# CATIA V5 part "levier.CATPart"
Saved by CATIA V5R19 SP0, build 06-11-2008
Part number: levier
Bounding box of the stored display mesh (mm): x -169.833 to 461.251, y 540.167 to 782.211, z -45 to 45
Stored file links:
  C:\Users\Thibaud\Desktop\IFMA\thinkmotion\IAO\modele_catia\levier.CATPart
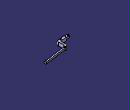
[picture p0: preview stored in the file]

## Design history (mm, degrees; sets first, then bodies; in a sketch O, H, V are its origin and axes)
Body1 (main body)
  Plane1: stored without definition
  Line1 to Line3: stored without definition
  Line4 "axe_pivot_levier_batit": stored without definition
  Line5 "axe_pivot_levier_bielette1": stored without definition
  Plane2: stored without definition
  Sketch1 on Plane1, origin (0, 0, 0), H (1, 0, 0), V (0, 1, 0)
    point P1 (-152.6433, 579.8246)
    line L1 (-152.6433, 579.8246) -> (12.2251, 601.807)
    line L2 (25.1111, 618.6579) -> (15.1988, 693)
    line L3 (40.9708, 726.7017) -> (60.7953, 729.345)
    line L4 (60.7953, 729.345) -> (64.7602, 699.6082)
    line L5 (64.7602, 699.6082) -> (59.8041, 698.9473)
    point P4 (44.9357, 696.9649)
    line L6 (46.9181, 682.0965) -> (58.152, 597.8421)
    point P5 (62.1169, 568.1053)
    line L7 (32.3801, 564.1404) -> (-147.3567, 540.1754)
    arc A1 centre (-150, 560) radius 20 from (-147.3567, 540.1754) to (-152.6433, 579.8246) cw
    point P7 (-150, 560)
    point P8 (-152.6433, 579.8246)
    reference projected line E1 (-150, 560) -> (0, 580) from Line2
    reference projected point E2 (-150, 560) from Line4
    reference projected point E3 (0, 580) from Line5
    arc A2 centre (28.4152, 593.8772) radius 30 from (58.152, 597.8421) to (32.3801, 564.1404) cw
    arc A3 centre (10.2427, 616.6754) radius 15 from (25.1111, 618.6579) to (12.2251, 601.807) cw
    arc A4 centre (61.7865, 684.0789) radius 15 from (59.8041, 698.9473) to (46.9181, 682.0965) ccw
    arc A5 centre (44.9357, 696.9649) radius 30 from (40.9708, 726.7017) to (15.1988, 693) ccw
    circle A6 centre (-150, 560) radius 10
    distance L1 L7 = 40
    distance L2 E3 = 30
    distance L6 L2 = 30
    distance L5 L3 = 30
    radius A2 = 30
    radius A3 = 15
    distance P4 P5 = 130
    radius A4 = 15
    radius A5 = 30
    radius A6 = 10
    distance L2 L4 = 50
    perpendicularity: L4 L3, L6 L7, L5 L6
    tangency: A1 L7, L1 A1, A2 L6, A2 L7, A3 L2, A3 L1, A4 L5, A4 L6, A5 L3, A5 L2
    parallelism: E1 L7
    coincidence: P1 P8, P7 E2, L7 P5, L5 P4, L6 P4, P5 L6
  Pad1: profile Sketch1, direction (0, 0, 1), length 30, mirrored extent
  Line6 "axe_pivot_levier_bielette1": stored without definition
  Sketch2 on Plane2, origin (0, 0, 0), H (1, 0, 0), V (0, 1, 0)
    circle A1 centre (0, 580) radius 10
    point P1 (0, 580)
    reference projected point E1 (0, 580) from Line6
    radius A1 = 10
    coincidence: P1 E1
  Pad2: profile Sketch2, direction (0, 0, 1), length 45, mirrored extent
  DatumSurface1
  Sketch3 on face of Pad1 from Sketch1.L4, origin (155.2808, 20.7041, 0), H (-0.1322, 0.9912, 0), V (0, 0, 1)
    line L1 (689.9122, 15) -> (714.9122, 15)
    line L2 (714.9122, 15) -> (714.9122, -15)
    line L3 (714.9122, -15) -> (689.9122, -15)
    line L4 (684.9122, -10) -> (684.9122, 10)
    reference projected line E1 (684.9122, -30) -> (684.9122, 30) from edge [face of Pad1 from Sketch1.L4 | face of Pad1 from Sketch1.L5]
    reference projected line E2 (714.9122, -30) -> (714.9122, 30) from edge [face of Pad1 from Sketch1.L3 | face of Pad1 from Sketch1.L4]
    reference projected line E3 (684.9122, 30) -> (714.9122, 30) from edge [face of Pad1 from Sketch1.L4 | end face of Pad1]
    arc A1 centre (689.9122, 10) radius 5 from (689.9122, 15) to (684.9122, 10) ccw
    arc A2 centre (689.9122, -10) radius 5 from (684.9122, -10) to (689.9122, -15) ccw
    distance E3 L1 = 15
    length L2 = 30
    radius A1 = 5
    radius A2 = 5
    horizontal: L1 H, L3 H
    vertical: L2 V, L4 V
    coincidence: L4 E1, E2 L2
    tangency: A1 L1, A1 L4, A2 L4, A2 L3
  Pad3: profile Sketch3, direction (0.9912, 0.1322, 0), length 400
  Fillet1: radius 5, on edge [face of Pad1 from Sketch1.L4 | face of Pad3 from Sketch3.L1]; edge [face of Pad1 from Sketch1.L4 | face of Pad3 from Sketch3.L3]
  Line7 "axe_pivot_levier_batit": stored without definition
  Line8 "axe_pivot_levier_batit": stored without definition
  Plane3: stored without definition
  Sketch4 on end face of Pad1, origin (0, 0, 30), H (1, 0, 0), V (0, 1, 0)
    line L1 (-87.8831, 548.1053) -> (-147.3567, 540.1754)
    arc A1 centre (-150, 560) radius 20 from (-147.3567, 540.1754) to (-152.6433, 579.8246) cw
    point P3 (-150, 560)
    line L2 (-152.6433, 579.8246) -> (-93.1696, 587.7544)
    line L3 (-93.1696, 587.7544) -> (-87.8831, 548.1053)
    reference projected line E1 (12.2251, 601.807) -> (-152.6433, 579.8246) from edge [face of Pad1 from Sketch1.L1 | end face of Pad1]
    reference projected line E2 (-147.3567, 540.1754) -> (32.3801, 564.1404) from edge [face of Pad1 from Sketch1.L7 | end face of Pad1]
    reference projected point E3 (-150, 560) from Line7
    reference projected point E4 (-150, 560) from Line8
    distance E4 L3 = 60
    tangency: A1 L1, L2 A1
    coincidence: L2 E1, L1 E2, P3 E3
    perpendicularity: L3 L1
  Pocket1: profile Sketch4, direction (0, 0, -1), length 15
  Mirror1: of Pocket1, about Plane3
